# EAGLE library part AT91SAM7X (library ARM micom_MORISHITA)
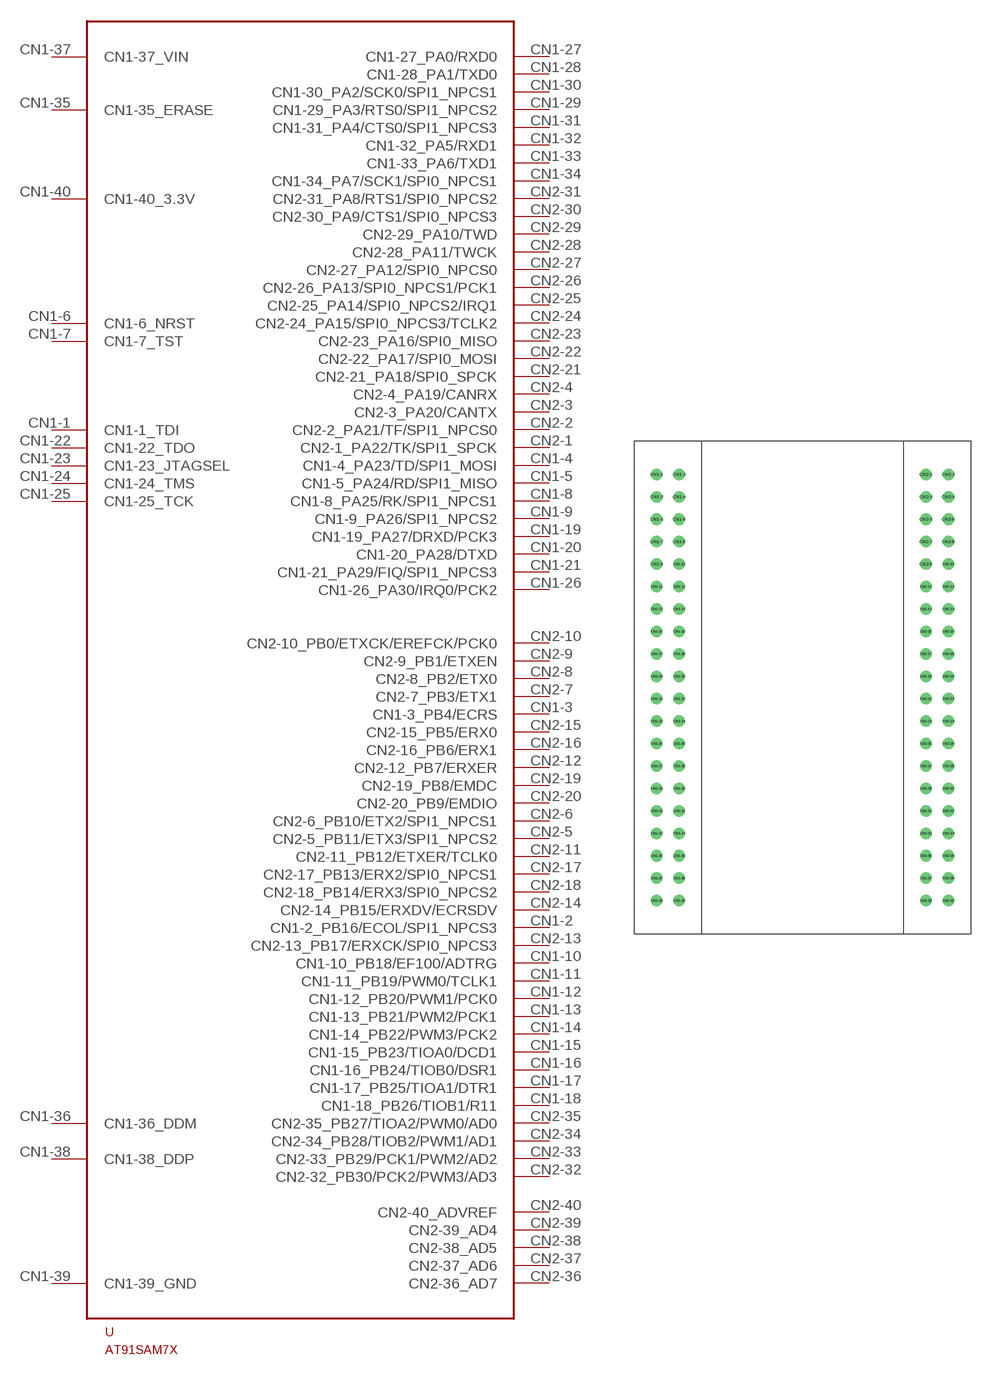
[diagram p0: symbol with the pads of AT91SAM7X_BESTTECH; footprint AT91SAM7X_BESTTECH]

Designator prefix U

## AT91SAM7XBESTTECH  [AT91SAM7X_BESTTECH]
CN1-1  CN1-1_TDI
CN1-2  CN1-2_PB16/ECOL/SPI1_NPCS3
CN1-3  CN1-3_PB4/ECRS
CN1-4  CN1-4_PA23/TD/SPI1_MOSI
CN1-5  CN1-5_PA24/RD/SPI1_MISO
CN1-6  CN1-6_NRST
CN1-7  CN1-7_TST
CN1-8  CN1-8_PA25/RK/SPI1_NPCS1
CN1-9  CN1-9_PA26/SPI1_NPCS2
CN1-10  CN1-10_PB18/EF100/ADTRG
CN1-11  CN1-11_PB19/PWM0/TCLK1
CN1-12  CN1-12_PB20/PWM1/PCK0
CN1-13  CN1-13_PB21/PWM2/PCK1
CN1-14  CN1-14_PB22/PWM3/PCK2
CN1-15  CN1-15_PB23/TIOA0/DCD1
CN1-16  CN1-16_PB24/TIOB0/DSR1
CN1-17  CN1-17_PB25/TIOA1/DTR1
CN1-18  CN1-18_PB26/TIOB1/R11
CN1-19  CN1-19_PA27/DRXD/PCK3
CN1-20  CN1-20_PA28/DTXD
CN1-21  CN1-21_PA29/FIQ/SPI1_NPCS3
CN1-22  CN1-22_TDO
CN1-23  CN1-23_JTAGSEL
CN1-24  CN1-24_TMS
CN1-25  CN1-25_TCK
CN1-26  CN1-26_PA30/IRQ0/PCK2
CN1-27  CN1-27_PA0/RXD0
CN1-28  CN1-28_PA1/TXD0
CN1-29  CN1-29_PA3/RTS0/SPI1_NPCS2
CN1-30  CN1-30_PA2/SCK0/SPI1_NPCS1
CN1-31  CN1-31_PA4/CTS0/SPI1_NPCS3
CN1-32  CN1-32_PA5/RXD1
CN1-33  CN1-33_PA6/TXD1
CN1-34  CN1-34_PA7/SCK1/SPI0_NPCS1
CN1-35  CN1-35_ERASE
CN1-36  CN1-36_DDM
CN1-37  CN1-37_VIN  pwr
CN1-38  CN1-38_DDP
CN1-39  CN1-39_GND  pwr
CN1-40  CN1-40_3.3V  pwr
CN2-1  CN2-1_PA22/TK/SPI1_SPCK
CN2-2  CN2-2_PA21/TF/SPI1_NPCS0
CN2-3  CN2-3_PA20/CANTX
CN2-4  CN2-4_PA19/CANRX
CN2-5  CN2-5_PB11/ETX3/SPI1_NPCS2
CN2-6  CN2-6_PB10/ETX2/SPI1_NPCS1
CN2-7  CN2-7_PB3/ETX1
CN2-8  CN2-8_PB2/ETX0
CN2-9  CN2-9_PB1/ETXEN
CN2-10  CN2-10_PB0/ETXCK/EREFCK/PCK0
CN2-11  CN2-11_PB12/ETXER/TCLK0
CN2-12  CN2-12_PB7/ERXER
CN2-13  CN2-13_PB17/ERXCK/SPI0_NPCS3
CN2-14  CN2-14_PB15/ERXDV/ECRSDV
CN2-15  CN2-15_PB5/ERX0
CN2-16  CN2-16_PB6/ERX1
CN2-17  CN2-17_PB13/ERX2/SPI0_NPCS1
CN2-18  CN2-18_PB14/ERX3/SPI0_NPCS2
CN2-19  CN2-19_PB8/EMDC
CN2-20  CN2-20_PB9/EMDIO
CN2-21  CN2-21_PA18/SPI0_SPCK
CN2-22  CN2-22_PA17/SPI0_MOSI
CN2-23  CN2-23_PA16/SPI0_MISO
CN2-24  CN2-24_PA15/SPI0_NPCS3/TCLK2
CN2-25  CN2-25_PA14/SPI0_NPCS2/IRQ1
CN2-26  CN2-26_PA13/SPI0_NPCS1/PCK1
CN2-27  CN2-27_PA12/SPI0_NPCS0
CN2-28  CN2-28_PA11/TWCK
CN2-29  CN2-29_PA10/TWD
CN2-30  CN2-30_PA9/CTS1/SPI0_NPCS3
CN2-31  CN2-31_PA8/RTS1/SPI0_NPCS2
CN2-32  CN2-32_PB30/PCK2/PWM3/AD3
CN2-33  CN2-33_PB29/PCK1/PWM2/AD2
CN2-34  CN2-34_PB28/TIOB2/PWM1/AD1
CN2-35  CN2-35_PB27/TIOA2/PWM0/AD0
CN2-36  CN2-36_AD7
CN2-37  CN2-37_AD6
CN2-38  CN2-38_AD5
CN2-39  CN2-39_AD4
CN2-40  CN2-40_ADVREF

## Footprint AT91SAM7X_BESTTECH (pad centres in mm)
AT91SAM7X Best Technology micom board ARM7 micom series. producted by ATMEL.Co
drill 0.8 round: CN1-1 -16.51,24.13; CN1-2 -13.97,24.13; CN1-3 -16.51,21.59; CN1-4 -13.97,21.59; CN1-5 -16.51,19.05; CN1-6 -13.97,19.05; CN1-7 -16.51,16.51; CN1-8 -13.97,16.51; CN1-9 -16.51,13.97; CN1-10 -13.97,13.97; CN1-11 -16.51,11.43; CN1-12 -13.97,11.43; CN1-13 -16.51,8.89; CN1-14 -13.97,8.89; CN1-15 -16.51,6.35; CN1-16 -13.97,6.35; CN1-17 -16.51,3.81; CN1-18 -13.97,3.81; CN1-19 -16.51,1.27; CN1-20 -13.97,1.27; CN1-21 -16.51,-1.27; CN1-22 -13.97,-1.27; CN1-23 -16.51,-3.81; CN1-24 -13.97,-3.81; CN1-25 -16.51,-6.35; CN1-26 -13.97,-6.35; CN1-27 -16.51,-8.89; CN1-28 -13.97,-8.89; CN1-29 -16.51,-11.43; CN1-30 -13.97,-11.43; CN1-31 -16.51,-13.97; CN1-32 -13.97,-13.97; CN1-33 -16.51,-16.51; CN1-34 -13.97,-16.51; CN1-35 -16.51,-19.05; CN1-36 -13.97,-19.05; CN1-37 -16.51,-21.59; CN1-38 -13.97,-21.59; CN1-39 -16.51,-24.13; CN1-40 -13.97,-24.13; CN2-1 13.97,24.13; CN2-2 16.51,24.13; CN2-3 13.97,21.59; CN2-4 16.51,21.59; CN2-5 13.97,19.05; CN2-6 16.51,19.05; CN2-7 13.97,16.51; CN2-8 16.51,16.51; CN2-9 13.97,13.97; CN2-10 16.51,13.97; CN2-11 13.97,11.43; CN2-12 16.51,11.43; CN2-13 13.97,8.89; CN2-14 16.51,8.89; CN2-15 13.97,6.35; CN2-16 16.51,6.35; CN2-17 13.97,3.81; CN2-18 16.51,3.81; CN2-19 13.97,1.27; CN2-20 16.51,1.27; CN2-21 13.97,-1.27; CN2-22 16.51,-1.27; CN2-23 13.97,-3.81; CN2-24 16.51,-3.81; CN2-25 13.97,-6.35; CN2-26 16.51,-6.35; CN2-27 13.97,-8.89; CN2-28 16.51,-8.89; CN2-29 13.97,-11.43; CN2-30 16.51,-11.43; CN2-31 13.97,-13.97; CN2-32 16.51,-13.97; CN2-33 13.97,-16.51; CN2-34 16.51,-16.51; CN2-35 13.97,-19.05; CN2-36 16.51,-19.05; CN2-37 13.97,-21.59; CN2-38 16.51,-21.59; CN2-39 13.97,-24.13; CN2-40 16.51,-24.13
